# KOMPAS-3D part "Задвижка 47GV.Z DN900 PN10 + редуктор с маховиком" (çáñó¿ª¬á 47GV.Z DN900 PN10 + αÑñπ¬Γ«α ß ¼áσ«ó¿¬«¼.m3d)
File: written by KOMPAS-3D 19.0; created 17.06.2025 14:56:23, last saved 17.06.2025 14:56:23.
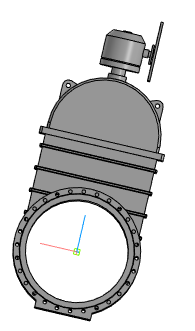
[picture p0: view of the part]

Document properties: Полное имя файла: Задвижка 47GV.Z DN900 PN10 + редуктор с маховиком.a3d

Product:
- Part/product: Задвижка 47GV.Z DN900 PN10 + редуктор с маховиком
    Масса: 3531.49

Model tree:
1. Операция без истории:1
